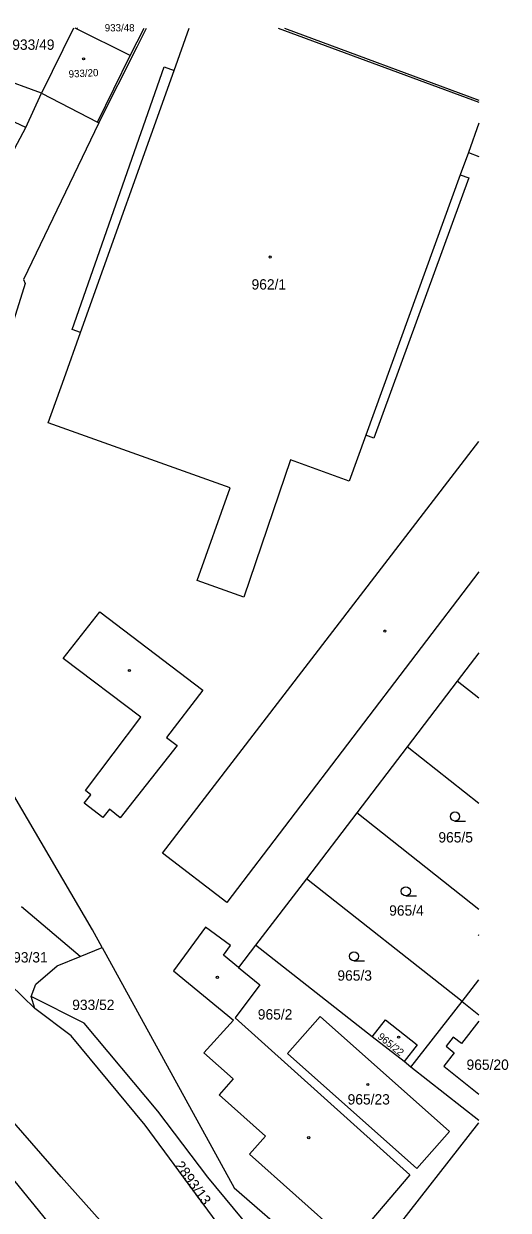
# Model space of a CAD drawing. Extents: x -496682 to -495907, y -1088575 to -1088018.
# Drawn here: x -496075.2 to -495995.5, y -1088214 to -1088018.8 of the extents above; entities that cross this region are included whole.
import ezdxf

# ---------------------------------------------------------------- set-up
doc = ezdxf.new("R2010")
doc.units = 0
for name, color, linetype in [('Hranice parcel', 7, 'Continuous'), ('Parcelní čísla', 7, 'Continuous'), ('Vnitřní kresba', 7, 'Continuous'), ('Značky budov', 7, 'Continuous'), ('Značky kultur', 7, 'Continuous')]:
    doc.layers.add(name, color=color, linetype=linetype)

msp = doc.modelspace()

# ---------------------------------------------------------------- linework, layer by layer
at = {"layer": 'Hranice parcel'}
for p, q in [((-496056.55, -1088022.57), (-496054.99, -1088019.49)), ((-496057.69, -1088024.02), (-496066.5, -1088019.6)), ((-496062.85, -1088035.07), (-496056.55, -1088022.57)), ((-496063.08, -1088034.95), (-496057.69, -1088024.02)), ((-496072.31, -1088030.21), (-496079.51, -1088027.56)), ((-496072.31, -1088030.21), (-496063.08, -1088034.95)), ((-496062.85, -1088035.07), (-496063.08, -1088034.95)), ((-496000.29, -1088122.28), (-496003.86, -1088126.96)), ((-496003.86, -1088126.96), (-496012.12, -1088137.77)), ((-496000.29, -1088129.77), (-496003.86, -1088126.96)), ((-496012.12, -1088137.77), (-496020.4, -1088148.62)), ((-496000.29, -1088147.11), (-496012.12, -1088137.77)), ((-496020.4, -1088148.62), (-496028.69, -1088159.46)), ((-496000.29, -1088164.52), (-496020.4, -1088148.62)), ((-496028.69, -1088159.46), (-496037.06, -1088170.42)), ((-496003.08, -1088179.67), (-496028.69, -1088159.46)), ((-496065.92, -1088172.25), (-496075.55, -1088164.09)), ((-496062.29, -1088170.76), (-496063.87, -1088167.88)), ((-496085.88, -1088168.81), (-496073.38, -1088180.81)), ((-496065.92, -1088172.25), (-496062.29, -1088170.76)), ((-496017.87, -1088185.46), (-496037.06, -1088170.42)), ((-496073.38, -1088180.81), (-496073.97, -1088178.85)), ((-496011.5, -1088190.46), (-496003.08, -1088179.67)), ((-496012.63, -1088189.57), (-496017.87, -1088185.46)), ((-496011.5, -1088190.46), (-496012.63, -1088189.57)), ((-496000.29, -1088199.24), (-496011.5, -1088190.46)), ((-496016.87, -1088220.82), (-496000.29, -1088199.63))]:
    msp.add_line(p, q, dxfattribs=at)
for points in [[(-496067.04, -1088019.49), (-496072.31, -1088030.21)], [(-496066.5, -1088019.6), (-496066.73, -1088019.49)], [(-496066.35, -1088019.49), (-496066.5, -1088019.6)], [(-496057.69, -1088024.02), (-496055.37, -1088019.49)], [(-496032.28, -1088019.49), (-496000.29, -1088031.36)], [(-496093.28, -1088059.84), (-496083.21, -1088051.44), (-496074.87, -1088035.85), (-496079.37, -1088033.74), (-496083.9, -1088032.61)], [(-496062.85, -1088035.07), (-496075.24, -1088060.86), (-496075, -1088061.51), (-496077.39, -1088069.25), (-496082.78, -1088067.93), (-496083.58, -1088068.36), (-496089.22, -1088083.77), (-496090.2, -1088086.33), (-496097.26, -1088083.87)], [(-496063.87, -1088167.88), (-496084, -1088133.61), (-496098.14, -1088107.2), (-496102.25, -1088098.03)], [(-496036.91, -1088246.54), (-496039.16, -1088242.24), (-496043.62, -1088236.85), (-496051.67, -1088227.99), (-496069.06, -1088208.54), (-496096.57, -1088176.99), (-496121.59, -1088147.94)], [(-496000.29, -1088168.82), (-496000.38, -1088168.75), (-496000.29, -1088168.63)], [(-496062.29, -1088170.76), (-496040.58, -1088210.35), (-496030.11, -1088219.42), (-496026.24, -1088224.83)], [(-496037.06, -1088170.42), (-496039.85, -1088174.07), (-496036.34, -1088176.91), (-496040.43, -1088182.38), (-496011.65, -1088208.22), (-496021.37, -1088219.61), (-496018, -1088222.26)], [(-496073.97, -1088178.85), (-496073.24, -1088176.82), (-496069.71, -1088173.81), (-496065.92, -1088172.25)], [(-496003.08, -1088179.67), (-496000.29, -1088176.09)], [(-496044.94, -1088208.57), (-496053.15, -1088197.69), (-496065.29, -1088183.21), (-496073.97, -1088178.85)], [(-496034.78, -1088226.85), (-496036.15, -1088225.48), (-496039.37, -1088221.52), (-496055.23, -1088200.01), (-496067.42, -1088185.33), (-496073.38, -1088180.81)], [(-496003.08, -1088179.67), (-496000.29, -1088181.88)], [(-496071.36, -1088215.79), (-496084.6, -1088199.6), (-496096.21, -1088183.01)], [(-496031.8, -1088188.22), (-496026.44, -1088182.15), (-496005.16, -1088201.08), (-496010.51, -1088207.13), (-496031.8, -1088188.22)], [(-496017.87, -1088185.46), (-496015.69, -1088182.67), (-496010.45, -1088186.78), (-496012.63, -1088189.57)], [(-496026.24, -1088224.83), (-496029.36, -1088224.99), (-496033.57, -1088222.31), (-496044.94, -1088208.57)]]:
    msp.add_lwpolyline(points, dxfattribs=at)
at = {"layer": 'Vnitřní kresba'}
for p, q in [((-496050.48, -1088026.47), (-496047.98, -1088019.49)), ((-496033.36, -1088019.49), (-496000.29, -1088031.68)), ((-496067.26, -1088069.07), (-496052.12, -1088025.87)), ((-496065.86, -1088069.57), (-496050.48, -1088026.47)), ((-496052.12, -1088025.87), (-496050.48, -1088026.47)), ((-496074.87, -1088035.85), (-496072.31, -1088030.21)), ((-496000.29, -1088035.14), (-496002.04, -1088039.97)), ((-496002.04, -1088039.97), (-496003.36, -1088043.61)), ((-496002.04, -1088039.97), (-496000.29, -1088040.61)), ((-496003.36, -1088043.61), (-496018.92, -1088086.49)), ((-496001.98, -1088044.1), (-496017.57, -1088086.96)), ((-496003.36, -1088043.61), (-496001.98, -1088044.1)), ((-496068.56, -1088077.13), (-496065.86, -1088069.57)), ((-496065.86, -1088069.57), (-496067.26, -1088069.07)), ((-496071.17, -1088084.43), (-496068.56, -1088077.13)), ((-496041.22, -1088095.12), (-496071.17, -1088084.43)), ((-496052.38, -1088155.28), (-496000.29, -1088087.52)), ((-496018.92, -1088086.49), (-496021.66, -1088094.05)), ((-496017.57, -1088086.96), (-496018.92, -1088086.49)), ((-496031.33, -1088090.54), (-496038.99, -1088113.12)), ((-496021.66, -1088094.05), (-496031.33, -1088090.54)), ((-496046.67, -1088110.38), (-496041.22, -1088095.12)), ((-496000.29, -1088108.99), (-496041.78, -1088163.38)), ((-496038.99, -1088113.12), (-496046.67, -1088110.38)), ((-496068.71, -1088123.24), (-496062.67, -1088115.54)), ((-496062.67, -1088115.54), (-496045.76, -1088128.45)), ((-496055.94, -1088132.87), (-496068.71, -1088123.24)), ((-496045.76, -1088128.45), (-496051.72, -1088136.21)), ((-496065.05, -1088144.97), (-496055.94, -1088132.87)), ((-496051.72, -1088136.21), (-496049.95, -1088137.53)), ((-496049.95, -1088137.53), (-496059.32, -1088149.42)), ((-496065.25, -1088147.03), (-496064.18, -1088145.65)), ((-496064.18, -1088145.65), (-496065.05, -1088144.97)), ((-496062.18, -1088149.39), (-496065.25, -1088147.03)), ((-496061.11, -1088148.03), (-496062.18, -1088149.39)), ((-496059.32, -1088149.42), (-496061.11, -1088148.03)), ((-496041.78, -1088163.38), (-496052.38, -1088155.28)), ((-496045.27, -1088167.44), (-496050.54, -1088174.65)), ((-496041.16, -1088170.45), (-496045.27, -1088167.44)), ((-496042.32, -1088172.06), (-496041.16, -1088170.45)), ((-496039.85, -1088174.07), (-496042.32, -1088172.06)), ((-496050.54, -1088174.65), (-496040.71, -1088182.76)), ((-496040.71, -1088182.76), (-496045.55, -1088188.12)), ((-496000.29, -1088182.9), (-496003.19, -1088186.57)), ((-496004.53, -1088185.53), (-496005.7, -1088187.02)), ((-496005.7, -1088187.02), (-496004.4, -1088188.13)), ((-496003.19, -1088186.57), (-496004.53, -1088185.53)), ((-496045.55, -1088188.12), (-496040.73, -1088192.39)), ((-496004.4, -1088188.13), (-496006.09, -1088190.31)), ((-496006.09, -1088190.31), (-496000.29, -1088194.91)), ((-496040.73, -1088192.39), (-496043.07, -1088195.03)), ((-496043.07, -1088195.03), (-496035.43, -1088201.81)), ((-496035.43, -1088201.81), (-496038.07, -1088204.78)), ((-496038.07, -1088204.78), (-496022.27, -1088218.83))]:
    msp.add_line(p, q, dxfattribs=at)
at = {"layer": 'Značky budov'}
for centre in [(-496065.36, -1088024.55), (-496034.66, -1088057.16), (-496015.78, -1088118.71), (-496057.82, -1088125.2), (-496043.34, -1088175.69), (-496013.51, -1088185.55), (-496018.58, -1088193.33), (-496028.31, -1088202.08)]:
    msp.add_circle(centre, 0.175, dxfattribs=at)
at = {"layer": 'Značky kultur'}
for p, q in [((-496004.24, -1088149.97), (-496002.49, -1088149.97)), ((-496012.33, -1088162.28), (-496010.58, -1088162.28)), ((-496020.86, -1088172.98), (-496019.11, -1088172.98))]:
    msp.add_line(p, q, dxfattribs=at)
for centre in [(-496004.24, -1088149.22), (-496012.33, -1088161.53), (-496020.86, -1088172.23)]:
    msp.add_circle(centre, 0.75, dxfattribs=at)

# ---------------------------------------------------------------- texts
at = {"layer": 'Parcelní čísla'}
for s, height, p in [('933/48', 1.2, (-496061.88, -1088020.03)), ('933/49', 1.7, (-496077.1, -1088023.06)), ('962/1', 1.7, (-496037.72, -1088062.51)), ('965/5', 1.7, (-496006.97, -1088153.5)), ('965/4', 1.7, (-496015.07, -1088165.54)), ('2893/31', 1.7, (-496079.48, -1088173.25)), ('965/3', 1.7, (-496023.59, -1088176.24)), ('933/52', 1.7, (-496067.23, -1088181.07)), ('965/2', 1.7, (-496036.69, -1088182.64)), ('965/20', 1.7, (-496002.34, -1088190.92)), ('965/23', 1.7, (-496021.91, -1088196.62))]:
    msp.add_text(s, height=height, dxfattribs=at).set_placement(p)
for s, height, rotation, p in [('933/20', 1.2, 3, (-496067.79, -1088027.64)), ('965/22', 1.2, 321, (-496017.07, -1088185.65)), ('2893/13', 1.7, 306, (-496050.46, -1088206.69))]:
    msp.add_text(s, height=height, rotation=rotation, dxfattribs=at).set_placement(p)

doc.saveas('drawing.dxf')
